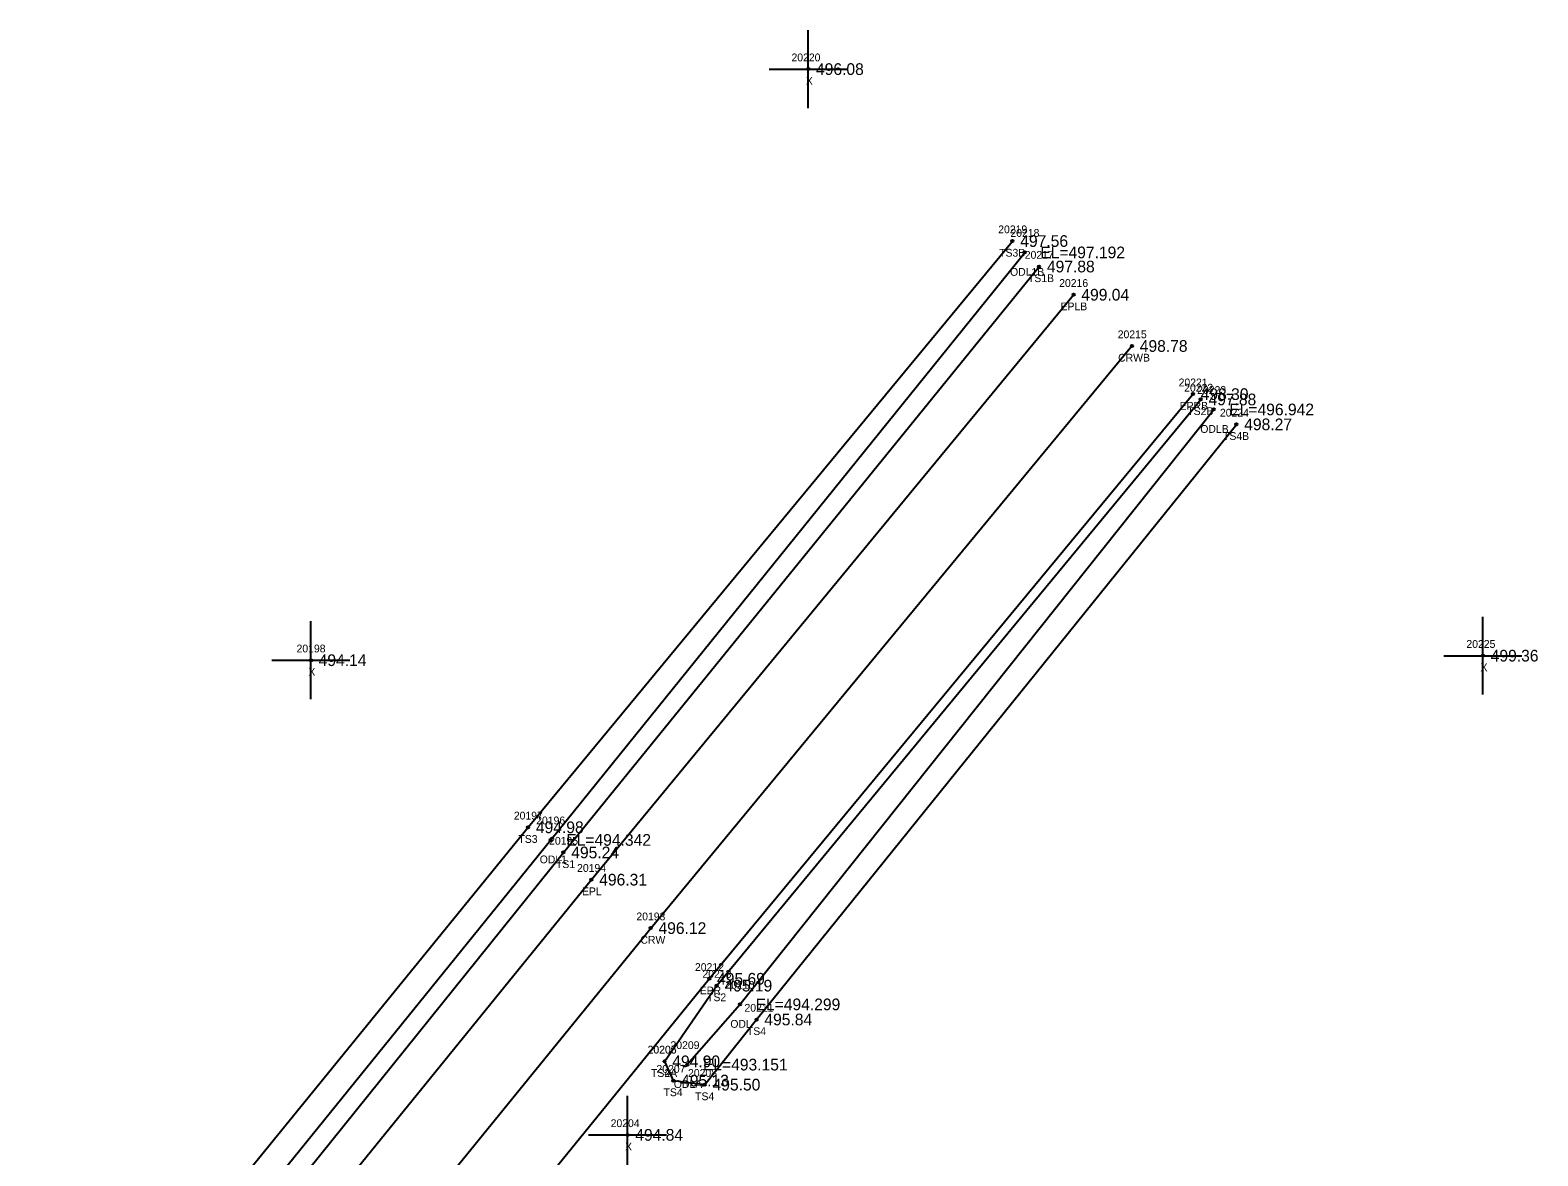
# Model space of a CAD drawing. Extents: x 1789565 to 1790548, y 909019 to 910194.
# Drawn here: x 1790354.5 to 1790548.1, y 910049.3 to 910193.8 of the extents above; entities that cross this region are included whole.
import ezdxf

# ---------------------------------------------------------------- set-up
doc = ezdxf.new("R2010")
doc.units = 0
for name, color, linetype in [('RD_DTM_BkLn1', 7, 'Continuous'), ('RD_DTM_BkLn2', 7, 'Continuous'), ('RD_DTM_BkLn_txCode', 7, 'Continuous'), ('RD_EX_H2O', 7, 'Continuous'), ('RD_EX_H2O_txCode', 7, 'Continuous'), ('RD_EX_Misc', 7, 'Continuous'), ('RD_EX_Misc_txCode', 7, 'Continuous'), ('RD_EX_Road', 7, 'Continuous'), ('RD_EX_Road_txCode', 7, 'Continuous'), ('RD_EX_TX_H2O_ELEV', 7, 'Continuous'), ('RD_EX_TX_Misc_ELEV', 7, 'Continuous'), ('RD_EX_TX_Road_ELEV', 7, 'Continuous'), ('RD_HC_Survey_ELEV', 7, 'Continuous'), ('RD_HC_Survey_txCode', 7, 'Continuous'), ('RD_SMD_Locator', 7, 'Continuous')]:
    doc.layers.add(name, color=color, linetype=linetype)

msp = doc.modelspace()

# ---------------------------------------------------------------- linework, layer by layer
at = {"layer": 'RD_DTM_BkLn1'}
msp.add_lwpolyline([(1790071.24, 909625.67), (1790132.78, 909702.56), (1790193.17, 909778.64), (1790254.11, 909855.13), (1790314.56, 909930.82), (1790375.87, 910006.79), (1790434.17, 910078.51), (1790495.95, 910153.23)], dxfattribs=at)
at = {"layer": 'RD_DTM_BkLn2'}
for points in [[(1790181.61, 909789.75), (1790181.34, 909795.67), (1790239.02, 909867.4), (1790301.11, 909943.25), (1790360.06, 910019.74), (1790418.43, 910091.45), (1790480.61, 910166.7)], [(1790060.69, 909634.71), (1790061.47, 909641.75), (1790119.6, 909713.74), (1790183.37, 909787.88), (1790244.44, 909862.78), (1790306.19, 909938.82), (1790365.07, 910016.23), (1790422.97, 910088.22), (1790484.03, 910163.43)], [(1790435.94, 910061.41), (1790442.64, 910071.13), (1790504.77, 910146.37)], [(1790435.94, 910061.41), (1790437.07, 910058.94), (1790441.11, 910058.42), (1790447.76, 910066.78), (1790509.36, 910143.17)]]:
    msp.add_lwpolyline(points, dxfattribs=at)
at = {"layer": 'RD_EX_H2O'}
for points in [[(1790181.61, 909789.75), (1790242.2, 909864.6), (1790303.39, 909941.16), (1790363.14, 910017.91), (1790421.33, 910089.83), (1790482.18, 910165.24)], [(1790438.87, 910060.99), (1790445.63, 910068.72), (1790506.44, 910145.08)]]:
    msp.add_lwpolyline(points, dxfattribs=at)
at = {"layer": 'RD_EX_Misc'}
for p, q in [((1790454.39, 910183.77), (1790454.39, 910193.77)), ((1790449.39, 910188.77), (1790459.39, 910188.77)), ((1790541, 910108.48), (1790541, 910118.48)), ((1790390.55, 910107.9), (1790390.55, 910117.9)), ((1790385.55, 910112.9), (1790395.55, 910112.9)), ((1790536, 910113.48), (1790546, 910113.48)), ((1790431.19, 910046.97), (1790431.19, 910056.97)), ((1790426.19, 910051.97), (1790436.19, 910051.97))]:
    msp.add_line(p, q, dxfattribs=at)
at = {"layer": 'RD_EX_Road'}
for points in [[(1790071.29, 909625.64), (1790063.58, 909631.76), (1790124.98, 909708.45), (1790186, 909785.5), (1790246.28, 909861.1), (1790307.38, 909937.59), (1790368.26, 910012.93), (1790426.56, 910084.73), (1790488.45, 910159.81)], [(1790071.25, 909625.72), (1790078.96, 909619.74), (1790139.76, 909696.36), (1790200.89, 909772.13), (1790261.64, 909848.6), (1790322.1, 909924.01), (1790383.38, 910000.26), (1790441.69, 910072.01), (1790503.77, 910147.05)]]:
    msp.add_lwpolyline(points, dxfattribs=at)
at = {"layer": 'RD_SMD_Locator'}
for centre in [(1790454.39, 910188.77), (1790480.61, 910166.7), (1790482.18, 910165.24), (1790484.03, 910163.43), (1790488.45, 910159.81), (1790495.95, 910153.23), (1790503.77, 910147.05), (1790504.77, 910146.37), (1790506.44, 910145.08), (1790509.36, 910143.17), (1790390.55, 910112.9), (1790541, 910113.48), (1790418.43, 910091.45), (1790421.33, 910089.83), (1790422.97, 910088.22), (1790426.56, 910084.73), (1790434.17, 910078.51), (1790441.69, 910072.01), (1790442.64, 910071.13), (1790445.63, 910068.72), (1790447.76, 910066.78), (1790435.94, 910061.41), (1790435.94, 910061.41), (1790438.87, 910060.99), (1790437.07, 910058.94), (1790441.11, 910058.42), (1790431.19, 910051.97)]:
    msp.add_circle(centre, 0.15, dxfattribs=at)

# ---------------------------------------------------------------- texts
at = {"layer": 'RD_DTM_BkLn_txCode'}
for s, p in [('20219', (1790478.78, 910167.7)), ('TS3B', (1790478.9, 910164.7)), ('20217', (1790482.19, 910164.43)), ('TS1B', (1790482.6, 910161.43)), ('20222', (1790502.65, 910147.37)), ('TS2B', (1790503.05, 910144.37)), ('20224', (1790507.24, 910144.17)), ('TS4B', (1790507.64, 910141.17)), ('20197', (1790416.6, 910092.45)), ('TS3', (1790417.19, 910089.45)), ('20195', (1790421.13, 910089.22)), ('TS1', (1790422.01, 910086.22)), ('20213', (1790440.81, 910072.13)), ('TS2', (1790441.4, 910069.13)), ('20211', (1790446.21, 910067.78)), ('TS4', (1790446.52, 910064.78)), ('20206', (1790433.76, 910062.41)), ('20205', (1790433.78, 910062.41)), ('TS2A', (1790434.21, 910059.41)), ('TS4A', (1790434.21, 910059.41)), ('20207', (1790434.91, 910059.94)), ('20208', (1790438.96, 910059.42)), ('TS4', (1790435.82, 910056.94)), ('TS4', (1790439.87, 910056.42))]:
    msp.add_text(s, height=1, dxfattribs=at).set_placement(p)
at = {"layer": 'RD_EX_H2O_txCode'}
for s, p in [('20218', (1790480.35, 910167.24)), ('ODL1B', (1790480.3, 910162.24)), ('20223', (1790504.32, 910147.08)), ('ODLB', (1790504.72, 910142.08)), ('20196', (1790419.47, 910091.83)), ('ODL1', (1790419.92, 910086.83)), ('20210', (1790443.76, 910070.72)), ('ODL', (1790444.39, 910065.72)), ('20209', (1790436.71, 910062.99)), ('ODLA', (1790437.14, 910057.99))]:
    msp.add_text(s, height=1, dxfattribs=at).set_placement(p)
at = {"layer": 'RD_EX_Misc_txCode'}
for s, p in [('20220', (1790452.24, 910189.77)), ('X', (1790454.08, 910186.77)), ('20198', (1790388.71, 910113.9)), ('20225', (1790538.88, 910114.48)), ('X', (1790390.23, 910110.9)), ('X', (1790540.69, 910111.48)), ('20204', (1790429.03, 910052.97)), ('X', (1790430.88, 910049.97))]:
    msp.add_text(s, height=1, dxfattribs=at).set_placement(p)
at = {"layer": 'RD_EX_Road_txCode'}
for s, p in [('20216', (1790486.6, 910160.81)), ('EPLB', (1790486.78, 910157.81)), ('20221', (1790501.94, 910148.05)), ('EPRB', (1790502.07, 910145.05)), ('20194', (1790424.72, 910085.73)), ('EPL', (1790425.35, 910082.73)), ('20212', (1790439.85, 910073.01)), ('EPR', (1790440.46, 910070.01))]:
    msp.add_text(s, height=1, dxfattribs=at).set_placement(p)
at = {"layer": 'RD_EX_TX_H2O_ELEV'}
for s, p in [('EL=497.192', (1790484.18, 910164.49)), ('EL=496.942', (1790508.44, 910144.33)), ('EL=494.342', (1790423.33, 910089.08)), ('EL=494.299', (1790447.63, 910067.97)), ('EL=493.151', (1790440.87, 910060.24))]:
    msp.add_text(s, height=1.5, dxfattribs=at).set_placement(p)
at = {"layer": 'RD_EX_TX_Misc_ELEV'}
for s, p in [('496.08', (1790455.39, 910188.02)), ('497.56', (1790481.61, 910165.95)), ('497.88', (1790485.03, 910162.68)), ('497.88', (1790505.77, 910145.62)), ('498.27', (1790510.36, 910142.42)), ('494.14', (1790391.55, 910112.15)), ('499.36', (1790542, 910112.73)), ('494.98', (1790419.43, 910090.7)), ('495.24', (1790423.97, 910087.47)), ('495.19', (1790443.64, 910070.38)), ('495.84', (1790448.76, 910066.03)), ('494.90', (1790436.94, 910060.66)), ('494.90', (1790436.94, 910060.66)), ('495.13', (1790438.07, 910058.19)), ('495.50', (1790442.11, 910057.67)), ('494.84', (1790432.19, 910051.22))]:
    msp.add_text(s, height=1.5, dxfattribs=at).set_placement(p)
at = {"layer": 'RD_EX_TX_Road_ELEV'}
for s, p in [('499.04', (1790489.45, 910159.06)), ('498.30', (1790504.77, 910146.3)), ('496.31', (1790427.56, 910083.98)), ('495.69', (1790442.69, 910071.26))]:
    msp.add_text(s, height=1.5, dxfattribs=at).set_placement(p)
at = {"layer": 'RD_HC_Survey_ELEV'}
for s, p in [('498.78', (1790496.95, 910152.48)), ('496.12', (1790435.17, 910077.76))]:
    msp.add_text(s, height=1.5, dxfattribs=at).set_placement(p)
at = {"layer": 'RD_HC_Survey_txCode'}
for s, p in [('20215', (1790494.12, 910154.23)), ('CRWB', (1790494.17, 910151.23)), ('20193', (1790432.33, 910079.51)), ('CRW', (1790432.85, 910076.51))]:
    msp.add_text(s, height=1, dxfattribs=at).set_placement(p)

doc.saveas('drawing.dxf')
